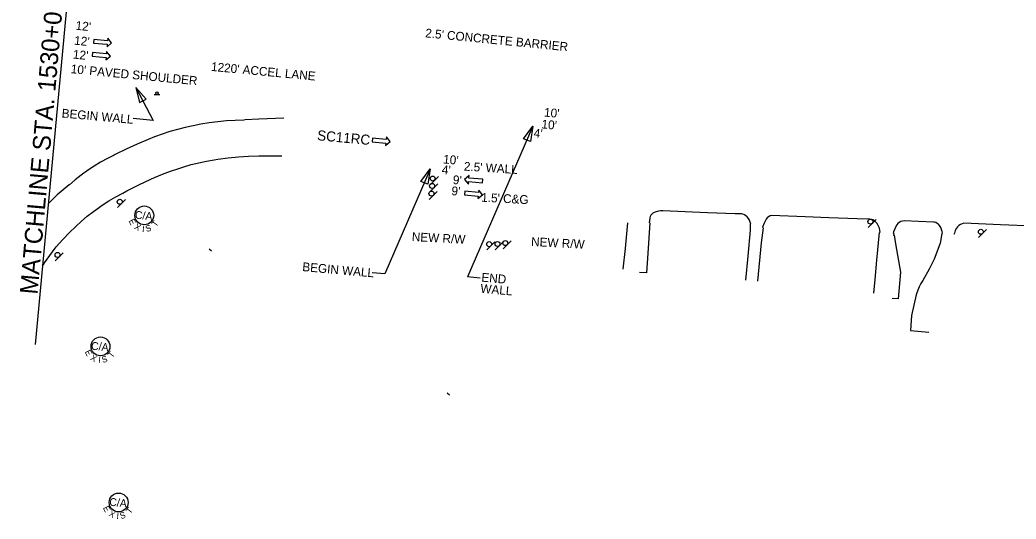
# Model space of a CAD drawing. Extents: x 1800374 to 1802004, y 1187708 to 1188617.
# Drawn here: x 1800374 to 1801167, y 1187752 to 1188150 of the extents above; entities that cross this region are included whole.
import ezdxf

# ---------------------------------------------------------------- set-up
doc = ezdxf.new("R2010")
doc.units = 0
for name, color, linetype in [('RD_EX_Road', 7, 'Continuous'), ('RD_PD_Final_LnLine', 7, 'Continuous'), ('RD_PD_Final_TX', 7, 'Continuous'), ('RD_PD_RW_TX', 7, 'Continuous'), ('RD_PD_WallFill', 7, 'Continuous'), ('RD_SHT_MatchLine', 7, 'Continuous'), ('RD_SHT_TX', 7, 'Continuous'), ('RD_Sketch8', 7, 'Continuous'), ('RD_TX_RoadID', 7, 'Continuous'), ('SN_P_Signs', 7, 'Continuous'), ('TERMINATOR', 7, 'Continuous')]:
    doc.layers.add(name, color=color, linetype=linetype)

# ---------------------------------------------------------------- blocks, each defined once
blk = doc.blocks.new('SARRW2')
at = {"layer": 'RD_PD_Final_LnLine'}
blk.add_lwpolyline([(-12, 1.2), (-12, -1.2), (-2.83, -1.2), (-2.83, -2.83), (0, 0), (-2.83, 2.83), (-2.83, 1.2)], close=True, dxfattribs=at)

msp = doc.modelspace()

# ---------------------------------------------------------------- linework, layer by layer
at = {"layer": 'RD_EX_Road'}
for points in [[(1800584.14, 1188071.18), (1800564.19, 1188070.47), (1800553.54, 1188069.85), (1800552.51, 1188069.78), (1800545.59, 1188069.58), (1800538.68, 1188069.14), (1800531.78, 1188068.47), (1800524.92, 1188067.56), (1800518.08, 1188066.42), (1800512.04, 1188065.2), (1800505.77, 1188063.89), (1800499.55, 1188062.35), (1800493.39, 1188060.58), (1800487.3, 1188058.59), (1800481.29, 1188056.37), (1800476.31, 1188054.34), (1800467.46, 1188050.53), (1800458.7, 1188046.51), (1800450.05, 1188042.28), (1800449.24, 1188041.87), (1800443.76, 1188039.1), (1800438.39, 1188036.13), (1800433.14, 1188032.96), (1800428.02, 1188029.58), (1800423.04, 1188026.01), (1800418.19, 1188022.25), (1800413.5, 1188018.31), (1800413.26, 1188018.1), (1800408.47, 1188014.2), (1800403.83, 1188010.12), (1800399.36, 1188005.86), (1800396.71, 1188003.14)], [(1800392.07, 1187953.54), (1800393.71, 1187956.04), (1800397.84, 1187961.94), (1800402.17, 1187967.7), (1800402.99, 1187968.75), (1800408.24, 1187974.56), (1800413.65, 1187980.2), (1800418.55, 1187985.02), (1800423.09, 1187989.16), (1800427.79, 1187993.12), (1800432.64, 1187996.89), (1800437.63, 1188000.47), (1800439.75, 1188001.91), (1800445.04, 1188005.36), (1800450.46, 1188008.62), (1800456, 1188011.67), (1800459.28, 1188013.34), (1800468.78, 1188018.12), (1800478.38, 1188022.69), (1800481.2, 1188023.99), (1800487.59, 1188026.65), (1800494.07, 1188029.08), (1800500.63, 1188031.3), (1800504.69, 1188032.54), (1800510.58, 1188034.31), (1800516.55, 1188035.85), (1800522.57, 1188037.17), (1800528.64, 1188038.25), (1800531.8, 1188038.71), (1800539.91, 1188039.74), (1800548.05, 1188040.54), (1800556.21, 1188041.09), (1800564.37, 1188041.41), (1800564.62, 1188041.42), (1800577.37, 1188041.37), (1800582.5, 1188041.25)], [(1800955.9, 1187986.92), (1800955.48, 1187988.51), (1800954.84, 1187990.02), (1800953.98, 1187991.42), (1800952.94, 1187992.69), (1800952.02, 1187993.55), (1800950.9, 1187994.25), (1800949.68, 1187994.74), (1800948.38, 1187995.01), (1800947.06, 1187995.04), (1800946.9, 1187995.03), (1800943.36, 1187995.18), (1800921.52, 1187995.86), (1800885.78, 1187997.46), (1800884.04, 1187997.47), (1800882.31, 1187997.25), (1800880.64, 1187996.79), (1800879.03, 1187996.11), (1800878.02, 1187995.54), (1800877.09, 1187994.82), (1800876.34, 1187993.94), (1800875.77, 1187992.92), (1800875.43, 1187991.8), (1800875.41, 1187991.7), (1800875.12, 1187987.87)], [(1801058.82, 1187980.35), (1801058.66, 1187982.09), (1801058.26, 1187983.78), (1801057.64, 1187985.41), (1801056.8, 1187986.93), (1801056.48, 1187987.41), (1801054.26, 1187989.62), (1801053.16, 1187990.21), (1801051.96, 1187990.58), (1801050.72, 1187990.73), (1801050.59, 1187990.73), (1801040.53, 1187991.07), (1801018.06, 1187991.91), (1800999.18, 1187992.72), (1800972.46, 1187993.89), (1800971.21, 1187993.45), (1800970.06, 1187992.79), (1800969.04, 1187991.93), (1800968.19, 1187990.91), (1800967.88, 1187990.42), (1800966.49, 1187987.55), (1800965.33, 1187984.6), (1800965.16, 1187984.11)], [(1800854.4, 1187951.07), (1800856.08, 1187967.52), (1800857.98, 1187988.01)], [(1800875.62, 1187987.83), (1800873.83, 1187963.74), (1800872.84, 1187948.18), (1800867.41, 1187948.38)], [(1800955.42, 1187986.79), (1800955.46, 1187982.16), (1800953.5, 1187961.5), (1800951.66, 1187942.21)], [(1801108.56, 1187979.41), (1801108.3, 1187981.1), (1801107.8, 1187982.73), (1801107.09, 1187984.28), (1801106.17, 1187985.72), (1801106.09, 1187985.82), (1801105.28, 1187986.76), (1801104.3, 1187987.53), (1801103.19, 1187988.11), (1801102, 1187988.46), (1801101.34, 1187988.56), (1801089.3, 1187989.08), (1801077.9, 1187989.49), (1801076.57, 1187989.3), (1801075.28, 1187988.88), (1801074.1, 1187988.24), (1801073.04, 1187987.4), (1801072.14, 1187986.39), (1801071.86, 1187985.98), (1801070.47, 1187983.16), (1801069.6, 1187980.83), (1801069.25, 1187979.51)], [(1801201.74, 1187973.73), (1801201.61, 1187975.46), (1801201.23, 1187977.16), (1801200.63, 1187978.8), (1801199.82, 1187980.34), (1801198.89, 1187981.64), (1801197.88, 1187982.69), (1801196.72, 1187983.57), (1801195.43, 1187984.24), (1801194.04, 1187984.7), (1801192.61, 1187984.93), (1801192.55, 1187984.93), (1801181.04, 1187985.29), (1801154.7, 1187986.38), (1801125.59, 1187987.61), (1801124.16, 1187987.2), (1801122.83, 1187986.58), (1801121.6, 1187985.74), (1801120.53, 1187984.73), (1801119.67, 1187983.62), (1801118.69, 1187981.78), (1801117.93, 1187979.84), (1801117.55, 1187978.57)], [(1800965.63, 1187983.95), (1800964.2, 1187972.13), (1800961.21, 1187941.36)], [(1801053.83, 1187931.9), (1801054.8, 1187942.9), (1801056.27, 1187958.1), (1801058.33, 1187980.31)], [(1801069.73, 1187979.37), (1801069.55, 1187978.15), (1801070.08, 1187978.05), (1801071.15, 1187971.29), (1801075.17, 1187948.64), (1801073.08, 1187927.49), (1801068.48, 1187927.74)], [(1801108.06, 1187979.33), (1801106.52, 1187971.64), (1801104.65, 1187966.69), (1801101.81, 1187959), (1801097.83, 1187951.12), (1801092.86, 1187942.09), (1801091.3, 1187939.57), (1801089.94, 1187936.93), (1801088.8, 1187934.19), (1801087.89, 1187931.37), (1801087.65, 1187930.49), (1801085.57, 1187922.23), (1801083.76, 1187914.11), (1801082.89, 1187902.27), (1801097.57, 1187900.97)]]:
    msp.add_lwpolyline(points, dxfattribs=at)
at = {"layer": 'RD_PD_Final_TX'}
for p, q in [((1800466.5, 1188095.7), (1800480.22, 1188069.56)), ((1800480.22, 1188069.56), (1800464.4, 1188070.97)), ((1800782.42, 1188064.84), (1800730.38, 1187944.85)), ((1800700.71, 1188030.76), (1800664.49, 1187947.26)), ((1800664.49, 1187947.26), (1800654.49, 1187948.15)), ((1800740.37, 1187943.96), (1800730.38, 1187944.85))]:
    msp.add_line(p, q, dxfattribs=at)
at = {"layer": 'RD_PD_WallFill'}
for p, q in [((1800524.8, 1187967.11), (1800526.77, 1187965.58)), ((1800714.2, 1187852.5), (1800716.18, 1187850.97))]:
    msp.add_line(p, q, dxfattribs=at)
at = {"layer": 'RD_SHT_MatchLine'}
msp.add_line((1800436.4, 1188427.36), (1800386.22, 1187890.97), dxfattribs=at)
at = {"layer": 'RD_Sketch8'}
for centre in [(1800473.14, 1187993.86), (1800438.26, 1187889.55), (1800452.75, 1187765.22)]:
    msp.add_circle(centre, 7.5, dxfattribs=at)
at = {"layer": 'SN_P_Signs'}
for p, q in [((1800480.99, 1188090.19), (1800485.49, 1188090.19)), ((1800700.92, 1188018.58), (1800707.29, 1188024.95)), ((1800700.48, 1188012.68), (1800706.84, 1188019.05)), ((1800699.95, 1188006.61), (1800706.32, 1188012.98)), ((1800451.82, 1188000.08), (1800458.19, 1188006.44)), ((1801049.3, 1187984.32), (1801055.67, 1187990.68)), ((1801137.25, 1187976.16), (1801143.62, 1187982.53)), ((1800745.91, 1187966.32), (1800752.27, 1187972.68)), ((1800752.52, 1187966.46), (1800758.88, 1187972.83)), ((1800758.77, 1187967.19), (1800765.13, 1187973.55)), ((1800402.33, 1187957.74), (1800408.7, 1187964.1))]:
    msp.add_line(p, q, dxfattribs=at)
for centre, radius in [((1800483.25, 1188091.2), 1), ((1800702.69, 1188023.21), 2), ((1800702.24, 1188017.31), 2), ((1800701.72, 1188011.24), 2), ((1800453.58, 1188004.71), 2), ((1801051.06, 1187988.94), 2), ((1801139.01, 1187980.79), 2), ((1800747.67, 1187970.94), 2), ((1800754.28, 1187971.09), 2), ((1800760.53, 1187971.81), 2), ((1800404.09, 1187962.36), 2)]:
    msp.add_circle(centre, radius, dxfattribs=at)
at = {"layer": 'TERMINATOR'}
for points in [[(1800474.73, 1188086.47), (1800466.5, 1188095.7), (1800469.42, 1188083.68)], [(1800775, 1188054.94), (1800782.42, 1188064.84), (1800780.53, 1188052.61)], [(1800693.2, 1188020.95), (1800700.63, 1188030.85), (1800698.73, 1188018.62)]]:
    msp.add_lwpolyline(points, close=True, dxfattribs=at)

# ---------------------------------------------------------------- block references
at = {"layer": 'RD_PD_Final_LnLine'}
for p, xscale, yscale, rotation in [((1800447.18, 1188131.25), 1.1999999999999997, 1.2000000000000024, -5.34432300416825), ((1800446.2, 1188120.75), 1.1999999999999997, 1.2000000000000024, -5.34432300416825), ((1800668.94, 1188052.62), 1.1999999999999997, 1.2000000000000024, -5.34432300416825), ((1800728.05, 1188022.53), 1.2, 1.2000000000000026, 174.65567699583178), ((1800742.44, 1188010.26), 1.2000000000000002, 1.2000000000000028, -5.34432300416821)]:
    msp.add_blockref('SARRW2', p, dxfattribs=dict(at, xscale=xscale, yscale=yscale, rotation=rotation))

# ---------------------------------------------------------------- texts
at = {"layer": 'RD_PD_Final_TX'}
for s, rotation, p in [("12'", 353.95121, (1800418.2, 1188141.83)), ("12'", 353.95121, (1800417.08, 1188129.94)), ("2.5' CONCRETE BARRIER", 354.40741, (1800696.51, 1188135.75)), ("12'", 353.95121, (1800416.05, 1188118.9)), ("10' PAVED SHOULDER", 354.54177, (1800414.39, 1188107.19)), ("1220' ACCEL LANE", 354.65568, (1800526.05, 1188109.01)), ('BEGIN WALL', 354.90568, (1800407.17, 1188071.87)), ("10'", 354.76418, (1800791.1, 1188072.65)), ("10'", 354.76418, (1800789.06, 1188063.24)), ("4'", 354.76418, (1800782.85, 1188056.11)), ("10'", 354.76418, (1800710.78, 1188035.32)), ("4'", 354.76418, (1800709.7, 1188026.98)), ("2.5' WALL", 356.35618, (1800727.34, 1188029.57)), ("9'", 354.76418, (1800718.49, 1188018.92)), ("9'", 354.76418, (1800717.36, 1188010.08)), ("1.5' C&G", 357.0259, (1800741.19, 1188004.79)), ('BEGIN WALL', 354.90568, (1800598.72, 1187949.57)), ('END ', 354.90568, (1800741.24, 1187941.17)), ('WALL', 354.90568, (1800740.45, 1187932.33))]:
    msp.add_text(s, height=7, rotation=rotation, dxfattribs=at).set_placement(p)
at = {"layer": 'RD_PD_RW_TX'}
for p in [(1800685.94, 1187973.47), (1800780.88, 1187969.58)]:
    msp.add_text('NEW R/W', height=7, rotation=356.90483, dxfattribs=at).set_placement(p)
at = {"layer": 'RD_SHT_TX'}
msp.add_text('MATCHLINE STA. 1530+00 SEE SHEET NO. SN45', height=14.1726, rotation=84.99841, dxfattribs=at).set_placement((1800388.14, 1187930.52))
at = {"layer": 'RD_Sketch8'}
for s, height, rotation, p in [('C/A', 6.25, 354.65568, (1800465.45, 1187991.29)), ('E', 5, 297.86692, (1800460.46, 1187989.5)), ('X', 5, 330.29629, (1800464.69, 1187983.43)), ('I', 5, 354.45629, (1800471.25, 1187980.73)), ('S', 5, 16.44812, (1800474.9, 1187980.57)), ('T', 5, 52.84082, (1800482.48, 1187984.24)), ('C/A', 6.25, 354.65568, (1800430.57, 1187886.97)), ('E', 5, 297.86692, (1800425.57, 1187885.19)), ('X', 5, 330.29629, (1800429.81, 1187879.11)), ('T', 5, 52.84082, (1800447.59, 1187879.93)), ('I', 5, 354.45629, (1800436.37, 1187876.42)), ('S', 5, 16.44812, (1800440.02, 1187876.25)), ('C/A', 6.25, 354.65568, (1800445.07, 1187762.64)), ('E', 5, 297.86692, (1800440.07, 1187760.86)), ('X', 5, 330.29629, (1800444.3, 1187754.78)), ('I', 5, 354.45629, (1800450.86, 1187752.09)), ('S', 5, 16.44812, (1800454.52, 1187751.92)), ('T', 5, 52.84082, (1800462.09, 1187755.6))]:
    msp.add_text(s, height=height, rotation=rotation, dxfattribs=at).set_placement(p)
at = {"layer": 'RD_TX_RoadID'}
msp.add_text('SC11RC', height=8, rotation=354.65568, dxfattribs=at).set_placement((1800610.5, 1188053.81))

doc.saveas('drawing.dxf')
